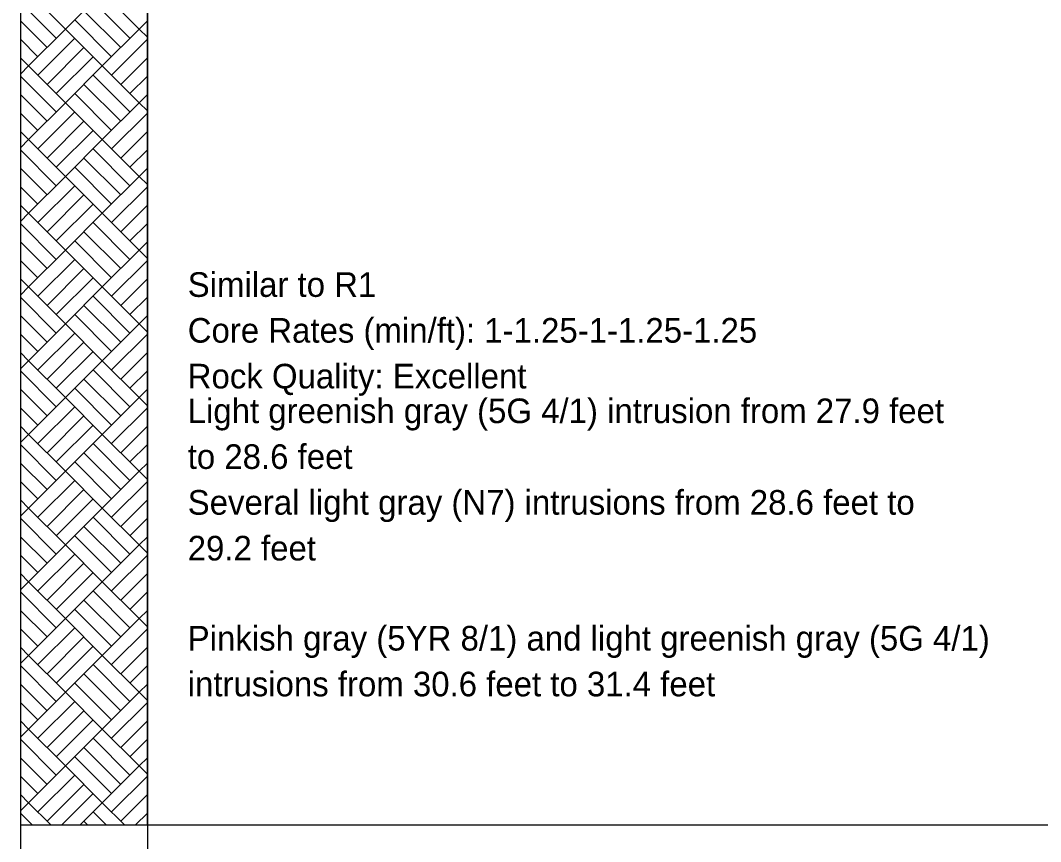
# Model space of a CAD drawing. Extents: x 9419 to 9552, y 6780 to 6865.
# Drawn here: x 9476.15 to 9485.37, y 6814.46 to 6821.89 of the extents above; entities that cross this region are included whole.
import ezdxf

# ---------------------------------------------------------------- set-up
doc = ezdxf.new("R2010")
doc.units = 0
doc.layers.add('7', color=7, linetype='Continuous')
doc.layers.add('8', color=7, linetype='Continuous')

msp = doc.modelspace()

# ---------------------------------------------------------------- linework, layer by layer
at = {"layer": '7'}
for p, q in [((9476.1476, 6822.0107), (9476.1476, 6814.6107)), ((9477.2959, 6814.6107), (9477.2959, 6822.0107)), ((9476.1476, 6814.6107), (9477.2959, 6814.6107))]:
    msp.add_line(p, q, dxfattribs=at)
for points in [[(9476.1476, 6822.0384), (9476.1476, 6796.9829)], [(9477.2959, 6822.0384), (9477.2959, 6796.9829)], [(9477.2959, 6814.6107), (9488.2385, 6814.6107)]]:
    msp.add_lwpolyline(points, dxfattribs=at)
at = {"layer": '8'}
for p, q in [((9476.2218, 6822.144), (9476.5551, 6821.8106)), ((9476.8884, 6822.144), (9476.5551, 6821.8106)), ((9476.8884, 6822.144), (9477.2218, 6821.8106)), ((9476.1476, 6822.0515), (9476.4718, 6821.7273)), ((9476.8051, 6822.0606), (9477.1384, 6821.7273)), ((9476.6384, 6821.894), (9476.9718, 6821.5606)), ((9476.7218, 6821.9773), (9477.0551, 6821.644)), ((9476.1476, 6821.8848), (9476.3884, 6821.644)), ((9476.5551, 6821.8106), (9476.2218, 6821.4773)), ((9476.5551, 6821.8106), (9476.2218, 6821.4773)), ((9476.8884, 6821.4773), (9476.5551, 6821.8106)), ((9476.5551, 6821.8106), (9476.8884, 6821.4773)), ((9477.2218, 6821.8106), (9476.8884, 6821.4773)), ((9477.2218, 6821.8106), (9476.8884, 6821.4773)), ((9477.2959, 6821.8848), (9477.2218, 6821.8106)), ((9477.2959, 6821.7365), (9477.2218, 6821.8106)), ((9477.2218, 6821.8106), (9477.2959, 6821.7365)), ((9476.1476, 6821.7181), (9476.3051, 6821.5606)), ((9476.6384, 6821.7273), (9476.3051, 6821.394)), ((9477.2959, 6821.7181), (9476.9718, 6821.394)), ((9476.7218, 6821.644), (9476.3884, 6821.3107)), ((9476.2218, 6821.4773), (9476.1476, 6821.5515)), ((9476.8051, 6821.5607), (9476.4718, 6821.2273)), ((9477.2959, 6821.5515), (9477.0551, 6821.3107)), ((9476.2218, 6821.4773), (9476.1476, 6821.4032)), ((9476.2218, 6821.4773), (9476.5551, 6821.144)), ((9476.8884, 6821.4773), (9476.5551, 6821.144)), ((9476.8884, 6821.4773), (9476.5551, 6821.144)), ((9476.8884, 6821.4773), (9477.2218, 6821.144)), ((9476.1476, 6821.3848), (9476.4718, 6821.0607)), ((9476.8051, 6821.394), (9477.1384, 6821.0607)), ((9477.2959, 6821.3848), (9477.1384, 6821.2273)), ((9476.7218, 6821.3107), (9477.0551, 6820.9773)), ((9476.1476, 6821.2181), (9476.3884, 6820.9773)), ((9476.6384, 6821.2273), (9476.9718, 6820.894)), ((9477.2959, 6821.2181), (9477.2218, 6821.144)), ((9477.2959, 6821.2181), (9477.2218, 6821.144)), ((9476.5551, 6821.144), (9476.2218, 6820.8107)), ((9476.5551, 6821.144), (9476.2218, 6820.8107)), ((9476.6384, 6821.0607), (9476.3051, 6820.7273)), ((9476.8884, 6820.8107), (9476.5551, 6821.144)), ((9476.5551, 6821.144), (9476.8884, 6820.8107)), ((9477.2218, 6821.144), (9476.8884, 6820.8107)), ((9477.2218, 6821.144), (9476.8884, 6820.8107)), ((9477.2959, 6821.0698), (9477.2218, 6821.144)), ((9477.2218, 6821.144), (9477.2959, 6821.0698)), ((9476.1476, 6821.0515), (9476.3051, 6820.894)), ((9476.7218, 6820.9773), (9476.3884, 6820.644)), ((9477.2959, 6821.0515), (9476.9718, 6820.7273)), ((9476.2218, 6820.8107), (9476.1476, 6820.8848)), ((9476.8051, 6820.894), (9476.4718, 6820.5607)), ((9477.2959, 6820.8848), (9477.0551, 6820.644)), ((9476.2218, 6820.8107), (9476.1476, 6820.7365)), ((9476.2218, 6820.8107), (9476.5551, 6820.4773)), ((9476.8884, 6820.8107), (9476.5551, 6820.4773)), ((9476.8884, 6820.8107), (9476.5551, 6820.4773)), ((9476.8884, 6820.8107), (9477.2218, 6820.4773)), ((9476.1476, 6820.7181), (9476.4718, 6820.394)), ((9476.8051, 6820.7273), (9477.1384, 6820.394)), ((9477.2959, 6820.7181), (9477.1384, 6820.5607)), ((9476.7218, 6820.644), (9477.0551, 6820.3107)), ((9476.1476, 6820.5515), (9476.3884, 6820.3107)), ((9476.6384, 6820.5607), (9476.9718, 6820.2273)), ((9477.2959, 6820.5515), (9477.2218, 6820.4773)), ((9477.2959, 6820.5515), (9477.2218, 6820.4773)), ((9476.5551, 6820.4773), (9476.2218, 6820.144)), ((9476.5551, 6820.4773), (9476.2218, 6820.144)), ((9476.8884, 6820.144), (9476.5551, 6820.4773)), ((9476.5551, 6820.4773), (9476.8884, 6820.144)), ((9477.2218, 6820.4773), (9476.8884, 6820.144)), ((9477.2218, 6820.4773), (9476.8884, 6820.144)), ((9477.2959, 6820.4032), (9477.2218, 6820.4773)), ((9477.2218, 6820.4773), (9477.2959, 6820.4032)), ((9476.1476, 6820.3848), (9476.3051, 6820.2273)), ((9476.6384, 6820.394), (9476.3051, 6820.0607)), ((9477.2959, 6820.3848), (9476.9718, 6820.0607)), ((9476.7218, 6820.3107), (9476.3884, 6819.9773)), ((9476.2218, 6820.144), (9476.1476, 6820.2181)), ((9476.2218, 6820.144), (9476.1476, 6820.0698)), ((9476.2218, 6820.144), (9476.5551, 6819.8107)), ((9476.8051, 6820.2273), (9476.4718, 6819.894)), ((9476.8884, 6820.144), (9476.5551, 6819.8107)), ((9476.8884, 6820.144), (9476.5551, 6819.8107)), ((9476.8884, 6820.144), (9477.2218, 6819.8107)), ((9477.2959, 6820.2181), (9477.0551, 6819.9773)), ((9476.1476, 6820.0515), (9476.4718, 6819.7273)), ((9476.8051, 6820.0607), (9477.1384, 6819.7273)), ((9477.2959, 6820.0515), (9477.1384, 6819.894)), ((9476.7218, 6819.9773), (9477.0551, 6819.644)), ((9476.1476, 6819.8848), (9476.3884, 6819.644)), ((9476.6384, 6819.894), (9476.9718, 6819.5607)), ((9477.2959, 6819.8848), (9477.2218, 6819.8107)), ((9477.2959, 6819.8848), (9477.2218, 6819.8107)), ((9476.5551, 6819.8107), (9476.2218, 6819.4773)), ((9476.5551, 6819.8107), (9476.2218, 6819.4773)), ((9476.8884, 6819.4773), (9476.5551, 6819.8107)), ((9476.5551, 6819.8107), (9476.8884, 6819.4773)), ((9477.2218, 6819.8107), (9476.8884, 6819.4773)), ((9477.2218, 6819.8107), (9476.8884, 6819.4773)), ((9477.2959, 6819.7365), (9477.2218, 6819.8107)), ((9477.2218, 6819.8107), (9477.2959, 6819.7365)), ((9476.1476, 6819.7181), (9476.3051, 6819.5607)), ((9476.6384, 6819.7273), (9476.3051, 6819.394)), ((9477.2959, 6819.7181), (9476.9718, 6819.394)), ((9476.7218, 6819.644), (9476.3884, 6819.3107)), ((9476.2218, 6819.4773), (9476.1476, 6819.5515)), ((9476.8051, 6819.5607), (9476.4718, 6819.2273)), ((9477.2959, 6819.5515), (9477.0551, 6819.3107)), ((9476.2218, 6819.4773), (9476.1476, 6819.4032)), ((9476.2218, 6819.4773), (9476.5551, 6819.144)), ((9476.8884, 6819.4773), (9476.5551, 6819.144)), ((9476.8884, 6819.4773), (9476.5551, 6819.144)), ((9476.8884, 6819.4773), (9477.2218, 6819.144)), ((9476.1476, 6819.3848), (9476.4718, 6819.0607)), ((9476.7218, 6819.3107), (9477.0551, 6818.9773)), ((9476.8051, 6819.394), (9477.1384, 6819.0607)), ((9477.2959, 6819.3848), (9477.1384, 6819.2273)), ((9476.1476, 6819.2181), (9476.3884, 6818.9773)), ((9476.6384, 6819.2273), (9476.9718, 6818.894)), ((9477.2959, 6819.2181), (9477.2218, 6819.144)), ((9477.2959, 6819.2181), (9477.2218, 6819.144)), ((9476.5551, 6819.144), (9476.2218, 6818.8107)), ((9476.5551, 6819.144), (9476.2218, 6818.8107)), ((9476.8884, 6818.8107), (9476.5551, 6819.144)), ((9476.5551, 6819.144), (9476.8884, 6818.8107)), ((9477.2218, 6819.144), (9476.8884, 6818.8107)), ((9477.2218, 6819.144), (9476.8884, 6818.8107)), ((9477.2959, 6819.0698), (9477.2218, 6819.144)), ((9477.2218, 6819.144), (9477.2959, 6819.0698)), ((9476.1476, 6819.0515), (9476.3051, 6818.894)), ((9476.6384, 6819.0607), (9476.3051, 6818.7273)), ((9477.2959, 6819.0515), (9476.9718, 6818.7273)), ((9476.7218, 6818.9773), (9476.3884, 6818.644)), ((9476.2218, 6818.8107), (9476.1476, 6818.8848)), ((9476.8051, 6818.894), (9476.4718, 6818.5607)), ((9477.2959, 6818.8848), (9477.0551, 6818.644)), ((9476.2218, 6818.8107), (9476.1476, 6818.7365)), ((9476.2218, 6818.8107), (9476.5551, 6818.4773)), ((9476.8884, 6818.8107), (9476.5551, 6818.4773)), ((9476.8884, 6818.8107), (9476.5551, 6818.4773)), ((9476.8884, 6818.8107), (9477.2218, 6818.4773)), ((9476.1476, 6818.7181), (9476.4718, 6818.394)), ((9476.8051, 6818.7273), (9477.1384, 6818.394)), ((9477.2959, 6818.7181), (9477.1384, 6818.5607)), ((9476.7218, 6818.644), (9477.0551, 6818.3107)), ((9476.1476, 6818.5515), (9476.3884, 6818.3107)), ((9476.5551, 6818.4773), (9476.2218, 6818.144)), ((9476.5551, 6818.4773), (9476.2218, 6818.144)), ((9476.8884, 6818.144), (9476.5551, 6818.4773)), ((9476.5551, 6818.4773), (9476.8884, 6818.144)), ((9476.6384, 6818.5607), (9476.9718, 6818.2273)), ((9477.2218, 6818.4773), (9476.8884, 6818.144)), ((9477.2218, 6818.4773), (9476.8884, 6818.144)), ((9477.2959, 6818.5515), (9477.2218, 6818.4773)), ((9477.2959, 6818.5515), (9477.2218, 6818.4773)), ((9477.2959, 6818.4032), (9477.2218, 6818.4773)), ((9477.2218, 6818.4773), (9477.2959, 6818.4032)), ((9476.6384, 6818.394), (9476.3051, 6818.0607)), ((9476.1476, 6818.3848), (9476.3051, 6818.2273)), ((9476.7218, 6818.3107), (9476.3884, 6817.9773)), ((9477.2959, 6818.3848), (9476.9718, 6818.0607)), ((9476.2218, 6818.144), (9476.1476, 6818.2181)), ((9476.8051, 6818.2273), (9476.4718, 6817.894)), ((9477.2959, 6818.2181), (9477.0551, 6817.9773)), ((9476.2218, 6818.144), (9476.1476, 6818.0698)), ((9476.2218, 6818.144), (9476.5551, 6817.8107)), ((9476.8884, 6818.144), (9476.5551, 6817.8107)), ((9476.8884, 6818.144), (9476.5551, 6817.8107)), ((9476.8884, 6818.144), (9477.2218, 6817.8107)), ((9476.1476, 6818.0515), (9476.4718, 6817.7273)), ((9476.8051, 6818.0607), (9477.1384, 6817.7273)), ((9477.2959, 6818.0515), (9477.1384, 6817.894)), ((9476.7218, 6817.9773), (9477.0551, 6817.644)), ((9476.1476, 6817.8848), (9476.3884, 6817.644)), ((9476.6384, 6817.894), (9476.9718, 6817.5607)), ((9477.2959, 6817.8848), (9477.2218, 6817.8107)), ((9477.2959, 6817.8848), (9477.2218, 6817.8107)), ((9476.5551, 6817.8107), (9476.2218, 6817.4773)), ((9476.5551, 6817.8107), (9476.2218, 6817.4773)), ((9476.8884, 6817.4773), (9476.5551, 6817.8107)), ((9476.5551, 6817.8107), (9476.8884, 6817.4773)), ((9477.2218, 6817.8107), (9476.8884, 6817.4773)), ((9477.2218, 6817.8107), (9476.8884, 6817.4773)), ((9477.2959, 6817.7365), (9477.2218, 6817.8107)), ((9477.2218, 6817.8107), (9477.2959, 6817.7365)), ((9476.1476, 6817.7181), (9476.3051, 6817.5607)), ((9476.6384, 6817.7273), (9476.3051, 6817.394)), ((9477.2959, 6817.7181), (9476.9718, 6817.394)), ((9476.7218, 6817.644), (9476.3884, 6817.3107)), ((9476.8051, 6817.5607), (9476.4718, 6817.2273)), ((9476.2218, 6817.4773), (9476.1476, 6817.5515)), ((9476.2218, 6817.4773), (9476.1476, 6817.4032)), ((9476.2218, 6817.4773), (9476.5551, 6817.144)), ((9476.8884, 6817.4773), (9476.5551, 6817.144)), ((9476.8884, 6817.4773), (9476.5551, 6817.144)), ((9476.8884, 6817.4773), (9477.2218, 6817.144)), ((9477.2959, 6817.5515), (9477.0551, 6817.3107)), ((9476.1476, 6817.3848), (9476.4718, 6817.0607)), ((9476.8051, 6817.394), (9477.1384, 6817.0607)), ((9477.2959, 6817.3848), (9477.1384, 6817.2273)), ((9476.7218, 6817.3107), (9477.0551, 6816.9773)), ((9476.1476, 6817.2181), (9476.3884, 6816.9773)), ((9476.6384, 6817.2273), (9476.9718, 6816.894)), ((9477.2959, 6817.2181), (9477.2218, 6817.144)), ((9477.2959, 6817.2181), (9477.2218, 6817.144)), ((9476.5551, 6817.144), (9476.2218, 6816.8107)), ((9476.5551, 6817.144), (9476.2218, 6816.8107)), ((9476.8884, 6816.8107), (9476.5551, 6817.144)), ((9476.5551, 6817.144), (9476.8884, 6816.8107)), ((9477.2218, 6817.144), (9476.8884, 6816.8107)), ((9477.2218, 6817.144), (9476.8884, 6816.8107)), ((9477.2959, 6817.0698), (9477.2218, 6817.144)), ((9477.2218, 6817.144), (9477.2959, 6817.0698)), ((9476.1476, 6817.0515), (9476.3051, 6816.894)), ((9476.6384, 6817.0607), (9476.3051, 6816.7273)), ((9477.2959, 6817.0515), (9476.9718, 6816.7273)), ((9476.7218, 6816.9773), (9476.3884, 6816.644)), ((9476.2218, 6816.8107), (9476.1476, 6816.8848)), ((9476.8051, 6816.894), (9476.4718, 6816.5607)), ((9477.2959, 6816.8848), (9477.0551, 6816.644)), ((9476.2218, 6816.8107), (9476.1476, 6816.7365)), ((9476.2218, 6816.8107), (9476.5551, 6816.4773)), ((9476.8884, 6816.8107), (9476.5551, 6816.4773)), ((9476.8884, 6816.8107), (9476.5551, 6816.4773)), ((9476.8051, 6816.7273), (9477.1384, 6816.394)), ((9476.8884, 6816.8107), (9477.2218, 6816.4773)), ((9476.1476, 6816.7181), (9476.4718, 6816.394)), ((9476.7218, 6816.644), (9477.0551, 6816.3107)), ((9477.2959, 6816.7181), (9477.1384, 6816.5607)), ((9476.1476, 6816.5515), (9476.3884, 6816.3107)), ((9476.6384, 6816.5607), (9476.9718, 6816.2273)), ((9477.2959, 6816.5515), (9477.2218, 6816.4773)), ((9477.2959, 6816.5515), (9477.2218, 6816.4773)), ((9476.5551, 6816.4773), (9476.2218, 6816.144)), ((9476.5551, 6816.4773), (9476.2218, 6816.144)), ((9476.8884, 6816.144), (9476.5551, 6816.4773)), ((9476.5551, 6816.4773), (9476.8884, 6816.144)), ((9477.2218, 6816.4773), (9476.8884, 6816.144)), ((9477.2218, 6816.4773), (9476.8884, 6816.144)), ((9477.2959, 6816.4032), (9477.2218, 6816.4773)), ((9477.2218, 6816.4773), (9477.2959, 6816.4032)), ((9476.1476, 6816.3848), (9476.3051, 6816.2273)), ((9476.6384, 6816.394), (9476.3051, 6816.0607)), ((9477.2959, 6816.3848), (9476.9718, 6816.0607)), ((9476.7218, 6816.3107), (9476.3884, 6815.9773)), ((9476.2218, 6816.144), (9476.1476, 6816.2181)), ((9476.8051, 6816.2273), (9476.4718, 6815.894)), ((9477.2959, 6816.2181), (9477.0551, 6815.9773)), ((9476.2218, 6816.144), (9476.1476, 6816.0698)), ((9476.2218, 6816.144), (9476.5551, 6815.8107)), ((9476.8884, 6816.144), (9476.5551, 6815.8107)), ((9476.8884, 6816.144), (9476.5551, 6815.8107)), ((9476.8884, 6816.144), (9477.2218, 6815.8107)), ((9476.1476, 6816.0515), (9476.4718, 6815.7273)), ((9476.8051, 6816.0607), (9477.1384, 6815.7273)), ((9477.2959, 6816.0515), (9477.1384, 6815.894)), ((9476.7218, 6815.9773), (9477.0551, 6815.644)), ((9476.1476, 6815.8848), (9476.3884, 6815.644)), ((9476.5551, 6815.8107), (9476.2218, 6815.4773)), ((9476.5551, 6815.8107), (9476.2218, 6815.4773)), ((9476.8884, 6815.4773), (9476.5551, 6815.8107)), ((9476.5551, 6815.8107), (9476.8884, 6815.4773)), ((9476.6384, 6815.894), (9476.9718, 6815.5607)), ((9477.2218, 6815.8107), (9476.8884, 6815.4773)), ((9477.2218, 6815.8107), (9476.8884, 6815.4773)), ((9477.2959, 6815.8848), (9477.2218, 6815.8107)), ((9477.2959, 6815.8848), (9477.2218, 6815.8107)), ((9477.2959, 6815.7365), (9477.2218, 6815.8107)), ((9477.2218, 6815.8107), (9477.2959, 6815.7365)), ((9476.1476, 6815.7181), (9476.3051, 6815.5607)), ((9476.6384, 6815.7273), (9476.3051, 6815.394)), ((9477.2959, 6815.7181), (9476.9718, 6815.394)), ((9476.7218, 6815.644), (9476.3884, 6815.3107)), ((9476.2218, 6815.4773), (9476.1476, 6815.5515)), ((9476.8051, 6815.5607), (9476.4718, 6815.2273)), ((9477.2959, 6815.5515), (9477.0551, 6815.3107)), ((9476.2218, 6815.4773), (9476.1476, 6815.4032)), ((9476.2218, 6815.4773), (9476.5551, 6815.144)), ((9476.8884, 6815.4773), (9476.5551, 6815.144)), ((9476.8884, 6815.4773), (9476.5551, 6815.144)), ((9476.8884, 6815.4773), (9477.2218, 6815.144)), ((9476.1476, 6815.3848), (9476.4718, 6815.0607)), ((9476.8051, 6815.394), (9477.1384, 6815.0607)), ((9477.2959, 6815.3848), (9477.1384, 6815.2273)), ((9476.7218, 6815.3107), (9477.0551, 6814.9773)), ((9476.1476, 6815.2181), (9476.3884, 6814.9773)), ((9476.6384, 6815.2273), (9476.9718, 6814.894)), ((9477.2959, 6815.2181), (9477.2218, 6815.144)), ((9477.2959, 6815.2181), (9477.2218, 6815.144)), ((9476.5551, 6815.144), (9476.2218, 6814.8107)), ((9476.5551, 6815.144), (9476.2218, 6814.8107)), ((9476.8884, 6814.8107), (9476.5551, 6815.144)), ((9476.5551, 6815.144), (9476.8884, 6814.8107)), ((9477.2218, 6815.144), (9476.8884, 6814.8107)), ((9477.2218, 6815.144), (9476.8884, 6814.8107)), ((9477.2959, 6815.0699), (9477.2218, 6815.144)), ((9477.2218, 6815.144), (9477.2959, 6815.0699)), ((9476.1476, 6815.0515), (9476.3051, 6814.894)), ((9476.6384, 6815.0607), (9476.3051, 6814.7273)), ((9476.7218, 6814.9773), (9476.3884, 6814.644)), ((9477.2959, 6815.0515), (9476.9718, 6814.7273)), ((9476.2218, 6814.8107), (9476.1476, 6814.8848)), ((9476.8051, 6814.894), (9476.5218, 6814.6107)), ((9477.2959, 6814.8848), (9477.0551, 6814.644)), ((9476.2218, 6814.8107), (9476.1476, 6814.7365)), ((9476.2218, 6814.8107), (9476.4218, 6814.6107)), ((9476.8884, 6814.8107), (9476.6884, 6814.6107)), ((9476.8884, 6814.8107), (9476.6884, 6814.6107)), ((9476.8884, 6814.8107), (9477.0884, 6814.6107)), ((9476.1476, 6814.7181), (9476.2551, 6814.6107)), ((9476.8051, 6814.7273), (9476.9218, 6814.6107)), ((9477.2959, 6814.7181), (9477.1884, 6814.6107)), ((9476.7218, 6814.644), (9476.7551, 6814.6107))]:
    msp.add_line(p, q, dxfattribs=at)

# ---------------------------------------------------------------- texts
at = {"layer": '7'}
for s, p in [('Similar to R1', (9477.6605, 6819.3879)), ('Core Rates (min/ft): 1-1.25-1-1.25-1.25', (9477.6605, 6818.9736)), ('Rock Quality: Excellent', (9477.6605, 6818.5594)), ('Light greenish gray (5G 4/1) intrusion from 27.9 feet', (9477.6605, 6818.2455)), ('to 28.6 feet', (9477.6605, 6817.8313)), ('Several light gray (N7) intrusions from 28.6 feet to', (9477.6605, 6817.4171)), ('29.2 feet', (9477.6605, 6817.0029)), ('Pinkish gray (5YR 8/1) and light greenish gray (5G 4/1)', (9477.6605, 6816.1879)), ('intrusions from 30.6 feet to 31.4 feet', (9477.6605, 6815.7737))]:
    msp.add_text(s, height=0.2228, dxfattribs=at).set_placement(p)

doc.saveas('drawing.dxf')
